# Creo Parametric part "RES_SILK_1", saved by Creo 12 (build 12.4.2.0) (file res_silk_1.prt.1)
Units: Custom; MM, KILOGRAM, SECS

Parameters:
  PTC_WM_ITERATION = "0"
  PTC_WM_VERSION = "-.0"
  PTC_WM_LIFECYCLE_STATE = "In Work"
  PTC_WM_LIFECYCLE = "MO_CADDocument"
  PTC_WM_CREATED_BY = "Maximilian Roepper (Z0017RMS: MO)"
  PTC_WM_CREATED_ON = "18-Sep-26 11:36:42 AM"
  PTC_WM_MODIFIED_BY = "Maximilian Roepper (Z0017RMS: MO)"
  PTC_WM_MODIFIED_ON = "18-Sep-26 11:36:46 AM"
  PDMLINKNUMBER = "PDM000071454861"
  PTC_WM_NAME = "res_silk_1.prt"
  PTC_WM_NUMBER = "PDM000071454861"

Other parameters: WEIGHT, WEIGHT_FACTOR, WEIGHT_ADD, _MASS_TEMP, _DIFF_TEMP, MC_ERRORS, SUPPLIER

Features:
  1. coordinate system
  2. datum plane "PRT_YZ"
  3. datum plane "PRT_XY"
  4. datum plane "PRT_XZ"
  5. coordinate system
  6. datum axis
  7. datum axis
  8. datum axis
  9. coordinate system
  10. imported feature

Other named items: PRT, SIEMENS_MO, DRW_VIEW_ORG, PRT_X, PRT_Y, PRT_Z, CS0, ROUGH_GROB

Layers: 00_STD_CSYS-KSYS, 01_STD_PLANES-EBENEN, 02_STD_AXES-ACHSEN, 03_STD_CSYS-KSYS, 24_IMPORT_FEAT-IMPORT_KE

Surfaces: 10 plane, 8 cylinder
